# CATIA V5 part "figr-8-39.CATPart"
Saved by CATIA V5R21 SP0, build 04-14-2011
Part number: Part2
Bounding box of the stored display mesh (mm): x -50 to 50, y -50 to 50, z 0 to 40
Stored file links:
  D:\CATIA V5R21 E-RESOURCES\CATIA-V5R21\catia-v5r21-prt\c08-catia-v5r20-prt\c08-catia-v5r21-figr-8-39.CATPart
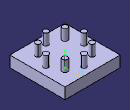
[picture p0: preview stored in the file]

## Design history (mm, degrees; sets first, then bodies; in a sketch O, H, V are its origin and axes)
Body1 (main body)
  Sketch1 on xy-plane, origin (0, 0, 0), H (1, 0, 0), V (0, 1, 0)
    line L1 (-50, 50) -> (50, 50)
    line L2 (50, 50) -> (50, -50)
    line L3 (50, -50) -> (-50, -50)
    line L4 (-50, -50) -> (-50, 50)
    axis line L5 (50, -50) -> (-50, 50)
    length L2 = 100
    length L3 = 100
    horizontal: L1 H, L3 H
    vertical: L2 V, L4 V
    midpoint: O L5
  Pad1: profile Sketch1, direction (0, 0, 1), length 20
  Sketch2 on face of Pad1, origin (0, 0, 20), H (1, 0, 0), V (0, 1, 0)
    circle A1 centre (0, -34.6458) radius 4.7511
    point P1 (0, -34.6458)
    coincidence: P1 V
  Pad2: profile Sketch2, direction (0, 0, 1), length 20
  CircPattern1: of Pad2, instances 8, angular step 45, axis from end face of Pad1
  Sketch3 on yz-plane, origin (0, 0, 0), H (0, 1, 0), V (0, 0, 1)
    line L1 (0, 0) -> (0, 20.0386)
    vertical: L1 V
